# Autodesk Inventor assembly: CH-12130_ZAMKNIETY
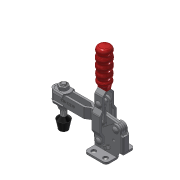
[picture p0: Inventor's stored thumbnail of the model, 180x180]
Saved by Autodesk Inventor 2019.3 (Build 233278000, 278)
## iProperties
Company: Î¢ÈíÖÐ¹ú
Created: 2012-09
Part Number: CH-12130_ZAMKNIETY
Material: Ogólny
Description: STEP AP203
Document SubType Name: Assembly
Designer: CADENGINEERING4
Sending System: SolidWorks 2010
Preprocessor: SwSTEP 2.0
Title: CH-12130.STEP
Author: Î¢ÈíÓÃ»§
Revision Number: ÈÎºÎ
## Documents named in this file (12)
- D:\Vault_2016\Projekty\NASZ KATALOG\CLAMPTEK\STRONA\Vertical toggle clamp\CH-12130\CH-12130_ZAMKNIETY.iam
- D:\Vault_2016\Projekty\NASZ KATALOG\CLAMPTEK\STEP FILES\Vertical toggle clamp\CH-12130\CH-FC-56212 Nut.ipt
- D:\Vault_2016\Projekty\NASZ KATALOG\CLAMPTEK\STEP FILES\Vertical toggle clamp\CH-12130\CH-12130-06.ipt
- D:\Vault_2016\Projekty\NASZ KATALOG\CLAMPTEK\STEP FILES\Vertical toggle clamp\CH-12130\CH-FW-516.ipt
- D:\Vault_2016\Projekty\NASZ KATALOG\CLAMPTEK\STEP FILES\Vertical toggle clamp\CH-12130\CH-12130-03 STRAIGHT HANDLE.ipt
- D:\Vault_2016\Projekty\NASZ KATALOG\CLAMPTEK\STEP FILES\Vertical toggle clamp\CH-12130\CH-12130-08.ipt
- D:\Vault_2016\Projekty\NASZ KATALOG\CLAMPTEK\STEP FILES\Vertical toggle clamp\CH-12130\CH-12130-07.ipt
- D:\Vault_2016\Projekty\NASZ KATALOG\CLAMPTEK\STEP FILES\Vertical toggle clamp\CH-12130\CH-12130-04 CONNECTING-PLATE.ipt
- D:\Vault_2016\Projekty\NASZ KATALOG\CLAMPTEK\STEP FILES\Vertical toggle clamp\CH-12130\CH-12130-05.ipt
- D:\Vault_2016\Projekty\NASZ KATALOG\CLAMPTEK\STEP FILES\Vertical toggle clamp\CH-12130\CH-12130-02 SHORT U-BAR.ipt
- D:\Vault_2016\Projekty\NASZ KATALOG\CLAMPTEK\STEP FILES\Vertical toggle clamp\CH-12130\CH-12130-01 FLANGED BASE.ipt
- D:\Vault_2016\Projekty\NASZ KATALOG\CLAMPTEK\STEP FILES\Vertical toggle clamp\CH-12130\CH-FC-56212 SPINDLE SUPPLIED.ipt
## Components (15 placed, 15 different names)
1. CH-FC-56212 Nut_1
2. CH-12130-06_2
3. CH-FC-56212 Nut_3
4. CH-FW-516_4
5. CH-12130-03 STRAIGHT HANDLE_5
6. CH-12130-08_6
7. CH-12130-07_7
8. CH-12130-06_8
9. CH-12130-04 CONNECTING-PLATE_9
10. CH-12130-05_10
11. CH-12130-02 SHORT U-BAR_11
12. CH-FW-516_12
13. CH-12130-08_13
14. CH-12130-01 FLANGED BASE_14
15. CH-FC-56212 SPINDLE SUPPLIED_15
